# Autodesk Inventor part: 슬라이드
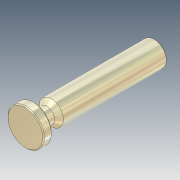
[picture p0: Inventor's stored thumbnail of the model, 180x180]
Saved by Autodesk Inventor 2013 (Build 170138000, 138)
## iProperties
Company: 한국ATC센터
Created: 2014-10
Part Number: 슬라이드
Document SubType Name: Modeling
Designer: 한국ATC센터
Density: 7.86 g/cm^3
Material: 강철, 연강
Mass: 735.303 g
Surface Area: 161.098 cm^2
Volume: 93.55 cm^3
Author: KYOUNG IL JANG
Revision Number: 1
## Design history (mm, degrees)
sketch "스케치1"
  geometry: L1 (-14, 195)-(-14, 171) reference; L2 (19, 106.5)-(-19, 106.5) reference; L3 (0, 106.5)-(0, 256.5); L4 (0, 256.5)-(-14, 256.5); L5 (-14, 256.5)-(-14, 136.5); L6 (-14, 116.5)-(-21, 116.5); L7 (-21, 116.5)-(-21, 106.5); L8 (-21, 106.5)-(0, 106.5); L9 (-14, 116.5)-(-9, 116.5); L10 (-9, 116.5)-(-9, 131.5); L11 (-9, 131.5)-(-14, 136.5); L12 (-14, 136.5)-(-14, 116.5); 1 further point
  constraints: 24 end point, 5 perpendicular, 3 parallel, 1 collinear, 1 horizontal, 1 midpoint, 1 point on line, 1 vertical, 4 other
  dimensions: "d0" = 10 distance between parallel lines of L6 L8; "d1" = 42 diameter of L7 L3; "d2" = 150 distance of L3.start L3.end; "d3" = 135 deg angle of L11 L5; "d4" = 18 diameter of L10 L3; "d5" = 30 distance from line of L5.end L8
revolve "회전1" sketch "스케치1" stored, may be unused: angle "d6" = 90 deg
chamfer "모따기1" distance "d7" = 1; stored, may be unused: second distance "d8" = 2, angle "d9" = 45 deg
fillet "모깎기1" dims "d10" = 2
node "솔리드1"
